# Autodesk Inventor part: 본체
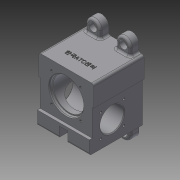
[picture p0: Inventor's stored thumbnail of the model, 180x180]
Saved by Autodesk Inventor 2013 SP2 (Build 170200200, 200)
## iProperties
Created: 2024-11
Part Number: 본체
Material: Generic
Document SubType Name: Modeling
Designer: a
Density: 1 g/cm^3
Author: a
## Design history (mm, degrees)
sketch "스케치1"
  geometry: L1 (-38, -42.5)-(38, -42.5); L2 (38, -42.5)-(38, 42.5); L3 (38, 42.5)-(-38, 42.5); L4 (-38, 42.5)-(-38, -42.5); L5 (-38, -42.5)-(38, 42.5); L6 (38, -42.5)-(-38, 42.5); 1 further point
  constraints: 12 end point, 2 midpoint, 2 parallel, 1 horizontal, 1 perpendicular
  dimensions: "d0" = 76 distance of L2.end L3.end; "d2" = 85 distance of L1.end L2.end
extrude "돌출1" new body sketch "스케치1" stored distance "d3" = 74; taper "d4" = 0 deg
sketch "스케치3"
  geometry: L1 (-38, 13.5)-(-36, 13.5); L2 (-36, 13.5)-(-36, -42.5); L3 (-36, -42.5)-(-38, -42.5); L4 (-38, -42.5)-(-38, 13.5); L5 (-38, 13.5)-(-36, -42.5); L6 (-36, 13.5)-(-38, -42.5); L7 (36, 13.5)-(38, 13.5); L8 (38, 13.5)-(38, -42.5); L9 (38, -42.5)-(36, -42.5); L10 (36, -42.5)-(36, 13.5); L11 (36, 13.5)-(38, -42.5); L12 (38, 13.5)-(36, -42.5); 3 further points
  constraints: 24 end point, 4 midpoint, 4 parallel, 2 horizontal, 2 perpendicular
  dimensions: "d10" = 2 distance of L1.start L1.end; "d12" = 2 distance of L7.start L7.end; "d13" = 56 distance of L1.end L2.end; "d14" = 56 distance of L9.end L7.start
extrude "돌출3" cut sketch "스케치3" stored distance "d15" = 74; taper "d16" = 0 deg
sketch "스케치5"
  geometry: L1 (-42.5, 37)-(42.5, 37) reference; L2 (42.5, 37)-(42.5, -37) reference; L3 (42.5, -37)-(-42.5, -37) reference; L4 (-42.5, -37)-(-42.5, 37) reference; L5 (42.5, 37)-(-23.5, 37); L6 (-23.5, 37)-(-23.5, 33); L7 (-23.5, 33)-(42.5, 33); L8 (42.5, 33)-(42.5, 37); L9 (42.5, 37)-(-23.5, 33); L10 (-23.5, 37)-(42.5, 33); 2 further points
  constraints: 12 end point, 2 midpoint, 2 parallel, 1 horizontal, 1 perpendicular
  dimensions: "d17" = 4 distance of L5.end L6.end; "d19" = 66 distance of L6.end L7.end
extrude "돌출4" cut sketch "스케치5" stored distance "d20" = 76; taper "d21" = 0 deg
sketch "스케치6"
  geometry: L1 (-36, -42.5)-(36, -42.5) reference; L2 (-6, -27.5)-(6, -27.5); L3 (6, -27.5)-(6, -42.5); L4 (6, -42.5)-(-6, -42.5); L5 (-6, -42.5)-(-6, -27.5); L6 (-6, -27.5)-(6, -42.5); L7 (6, -27.5)-(-6, -42.5); 4 further points
  constraints: 12 end point, 5 midpoint, 2 parallel, 1 horizontal, 1 perpendicular, 1 vertical alignment
  dimensions: "d22" = 12 distance of L2.start L2.end; "d24" = 15 distance of L2.end L3.end
extrude "돌출5" cut sketch "스케치6" stored distance "d25" = 76; taper "d26" = 0 deg
sketch "스케치7"
  geometry: L1 (-23.5, 33)-(42.5, 33) reference; L2 (42.5, 33)-(42.5, -37) reference; L3 (42.5, -37)-(-27.5, -37) reference; L4 (-27.5, -37)-(-27.5, 37) reference; L5 (-27.5, 37)-(-23.5, 37) reference; L6 (-23.5, 37)-(-23.5, 33) reference; L7 (9.5, 33)-(9.5, -33); L8 (9.5, -33)-(24.5, -33); L9 (24.5, -33)-(24.5, -30); L10 (24.5, -30)-(27, -30); L11 (27, -30)-(27, -19); L12 (27, -19)-(31.5, -19); L13 (31.5, -19)-(31.5, 29); L14 (31.5, 29)-(33, 29); L15 (33, 29)-(33, 33); L16 (33, 33)-(9.5, 33); 1 further point
  constraints: 20 end point, 9 parallel, 1 midpoint, 1 perpendicular
  dimensions: "d35" = 33 distance from line of L7.start L2; "d36" = 47 diameter of L15 L7; "d37" = 44 diameter of L13 L7; "d38" = 35 diameter of L11 L7; "d39" = 30 diameter of L9 L7; "d40" = 4 distance of L14.end L15.end; "d41" = 11 distance of L10.end L11.end; "d42" = 3 distance of L8.end L9.end; "d43" = 66 distance of L7.start L7.end
revolve "회전1" sketch "스케치7" stored, may be unused: angle "d44" = 90 deg
sketch "스케치9"
  geometry: L1 (0, -29)-(0, 0) reference; L2 (9.5, -33)-(66.5, -33); L3 (38, -4.5)-(38, -61.5); L4 (38, -33)-(17.847, -12.847); C1 r 23.5 at (38, -33) reference; A1 r 28.5 centre (38, -33) between (9.5, -33) and (66.5, -33); 2 further points
  constraints: 6 end point, 5 point on circle, 2 coincident, 2 perpendicular, 1 centre point
  dimensions: "d47" = 57 diameter of A1; "d50" = 45 deg angle of L3 L4
hole "구멍1" sketch "스케치9" at (17.847, -12.847) diameter "d52" = 3.242; stored, may be unused: countersink angle "d56" = 90 deg, drill point angle "d58" = 118 deg; dims "d53" = 8, "d54" = 4, "d55" = 2, "d57" = 10
sketch "스케치11"
  geometry: L1 (-27.5, -37)-(-27.5, 37) reference; L2 (-27.5, 37)-(-23.5, 37) reference; L3 (-23.5, 37)-(-23.5, 33) reference; L4 (-23.5, 33)-(-14, 33) reference; L5 (-14, 33)-(-14, 29) reference; L6 (-14, 29)-(-12.5, 29) reference; L7 (-12.5, 29)-(-12.5, -19) reference; L8 (-12.5, -19)-(-8, -19) reference; L9 (-8, -19)-(-8, -30) reference; L10 (-8, -30)-(-5.5, -30) reference; L11 (-5.5, -30)-(-5.5, -33) reference; L12 (-5.5, -33)-(24.5, -33) reference; L13 (24.5, -33)-(24.5, -30) reference; L14 (24.5, -30)-(27, -30) reference; L15 (27, -30)-(27, -19) reference; L16 (27, -19)-(31.5, -19) reference; L17 (31.5, -19)-(31.5, 29) reference; L18 (31.5, 29)-(33, 29) reference; L19 (33, 29)-(33, 33) reference; L20 (33, 33)-(42.5, 33) reference; L21 (42.5, 33)-(42.5, -37) reference; L22 (42.5, -37)-(-27.5, -37) reference; L23 (-14, 33)-(33, 33) reference; L24 (9.5, 33)-(9.5, -37); C1 r 16.5 at (-14.5, 5); 1 further point
  constraints: 2 end point, 1 centre point, 1 midpoint, 1 perpendicular, 1 point on line
  dimensions: "d62" = 33 diameter of C1; "d63" = 42 distance from line of C1.centre L22; "d65" = 24 distance from line of C1.centre L24
extrude "돌출6" cut sketch "스케치11" stored distance "d66" = 76; taper "d67" = 0 deg
sketch "스케치12"
  geometry: L1 (74, 19)-(70, 19) reference; L2 (25.5, 28)-(58.5, 28); L3 (42, 44.5)-(42, 11.5); L4 (42, 28)-(58, 12); A1 r 16.5 centre (42, 28) between (25.5, 28) and (58.5, 28) reference; 1 further point
  constraints: 6 end point, 4 point on circle, 1 parallel, 1 perpendicular
  dimensions: "d69" = 16 distance from line of L4.end L2; "d70" = 16 horizontal distance of L4.end L4.start; "d71" = 45 deg angle of L2 L4
hole "구멍2" sketch "스케치12" at (58, 12) diameter "d72" = 3.242; stored, may be unused: countersink angle "d76" = 90 deg, drill point angle "d78" = 118 deg; dims "d73" = 8, "d74" = 4, "d75" = 2, "d77" = 10
sketch "스케치13"
  geometry: L1 (38, 42.5)-(-38, 42.5) reference; L2 (-11, 52.5)-(-31, 52.5); L3 (-31, 52.5)-(-31, 42.5); L4 (-31, 42.5)-(-11, 42.5); L5 (-11, 42.5)-(-11, 52.5); L6 (-11, 52.5)-(-31, 42.5); L7 (-31, 52.5)-(-11, 42.5); A1 r 10 centre (-21, 52.5) between (-11, 52.5) and (-31, 52.5); 4 further points
  constraints: 12 end point, 4 midpoint, 2 parallel, 2 point on circle, 1 centre point, 1 coincident, 1 horizontal, 1 perpendicular, 1 point on line
  dimensions: "d82" = 21 horizontal distance of point (0, 0) point (-21, 42.5); "d83" = 20 distance of L3.end L4.end; "d84" = 10 distance between parallel lines of L4 L2
extrude "돌출7" join sketch "스케치13" distance "d85" = 12; taper "d86" = 0 deg
sketch "스케치14"
  geometry: A1 r 10 centre (0, 0) between (10, 0) and (-10, 0) reference; 2 further points
  constraints: 1 coincident
hole "구멍3" sketch "스케치14" at (0, 0) diameter "d87" = 6.6; stored, may be unused: countersink angle "d91" = 90 deg, drill point angle "d93" = 0 deg; dims "d88" = 8, "d89" = 11, "d90" = 6.6, "d92" = 10
chamfer "모따기1" distance "d96" = 1; stored, may be unused: second distance "d97" = 2, angle "d98" = 45 deg
chamfer "모따기2" distance "d99" = 1; stored, may be unused: second distance "d100" = 2, angle "d101" = 45 deg
fillet "모깎기1" dims "d102" = 3
fillet "모깎기2" dims "d103" = 3
fillet "모깎기3" dims "d104" = 3
fillet "모깎기4" dims "d105" = 3
fillet "모깎기5" dims "d106" = 3
chamfer "모따기3" distance "d107" = 1; stored, may be unused: second distance "d108" = 2, angle "d109" = 45 deg
fillet "모깎기6" dims "d110" = 3
sketch "스케치17"
  geometry: L1 (0, 0)-(12, 0) reference; L2 (-30, 0)-(0, 0) reference; L3 (0, 0)-(12, 0) reference; L4 (12, 0)-(42, 0) reference; L5 (42, 0)-(42, -20.285) reference; L6 (41, -21.839)-(12, -21.839) reference; L7 (12, -21.839)-(0, -21.839) reference; L8 (0, -21.839)-(-29, -21.839) reference; L9 (-30, -20.285)-(-30, 0) reference; L10 (0, 0)-(0, -21.839) reference; L11 (12, -21.839)-(12, 0) reference; L12 (12, -74)-(12, -42.161) reference; L13 (0, -42.161)-(12, -42.161) reference; L14 (-29, -42.161)-(0, -42.161) reference; L15 (-30, -74)-(-30, -43.715) reference; L16 (0, -74)-(-30, -74) reference; L17 (0, -42.161)-(0, -74) reference; L18 (12, -74)-(0, -74) reference; L19 (42, -74)-(12, -74) reference; L20 (42, -43.715)-(42, -74) reference; L21 (12, -42.161)-(41, -42.161) reference; 3 further points
  constraints: 2 vertical alignment, 4 other
  dimensions: "d111" = 12 distance from line of point (6, -12) L1; "d112" = 40 distance of point (6, -52) point (6, -12)
hole "구멍4" sketch "스케치17" at (6, -12), (6, -52) diameter "d113" = 3.242; stored, may be unused: countersink angle "d117" = 90 deg, drill point angle "d119" = 118 deg; dims "d114" = 8, "d115" = 11, "d116" = 6.6, "d118" = 10
node "작업 평면1"
sketch "스케치18"
  geometry: L1 (20.74, 8.113)-(-20.74, 8.113); L2 (-20.74, 8.113)-(-20.74, 17.887); L3 (-20.74, 17.887)-(20.74, 17.887); L4 (20.74, 17.887)-(20.74, 8.113); L5 (20.74, 13)-(-20.74, 13); L6 (0, 8.113)-(0, 17.887); L7 (35, 33)-(-35, 33) reference; 2 further points
  constraints: 5 midpoint, 4 end point, 1 vertical alignment, 2 other
  dimensions: "d121" = 20 distance from line of L5.end L7
feature "엠보싱1" sketch "스케치18" dims "d0" = 76, "d2" = 85, "d122" = 0.5, "d123" = 0
node "솔리드1"
pattern_circular "원형 패턴1" dims angle "d60" = 360 deg
pattern_circular "원형 패턴2" dims angle "d80" = 360 deg
mirror "대칭1"
mirror "대칭2"
mirror "대칭3"
mirror "대칭4"
mirror "대칭5"
node "절단 모서리 투영2"
node "절단 모서리 투영3"
node "절단 모서리 투영4"
node "절단 모서리 투영7"
other parameters: "d120" = 50.5
